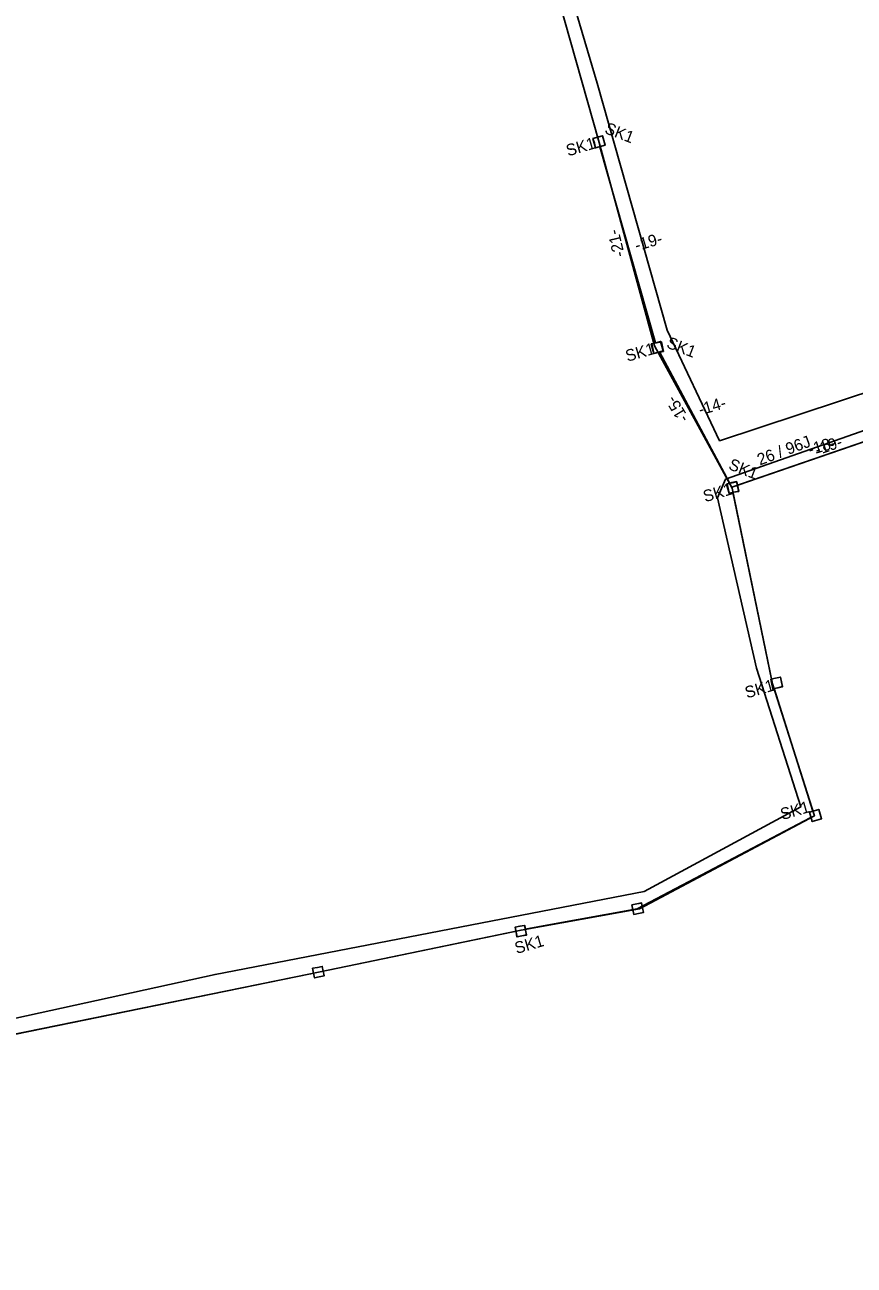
# Model space of a CAD drawing. Extents: x 6494530 to 6506885, y 5884901 to 5892312.
# Drawn here: x 6497551.9 to 6497628.3, y 5889363.3 to 5889477.6 of the extents above; entities that cross this region are included whole.
import ezdxf

# ---------------------------------------------------------------- set-up
doc = ezdxf.new("R2010")
doc.units = 0
for name, color, linetype in [('Gminne - nazwy', 7, 'Continuous'), ('kabel OTK do tablicy VMS', 7, 'Continuous'), ('nr  istniejącego kabla otk', 7, 'Continuous'), ('POWIATOWE', 7, 'Continuous'), ('studnie do wyrysu', 7, 'Continuous'), ('trasa kanalizacji do wyrysu', 7, 'Continuous'), ('W ISTN OTK96J', 7, 'Continuous'), ('Warstwa 59', 7, 'Continuous'), ('WOJEWÓDZKIE', 7, 'Continuous')]:
    doc.layers.add(name, color=color, linetype=linetype)

# ---------------------------------------------------------------- blocks, each defined once
blk = doc.blocks.new('ELARM2_28')
at = {"layer": 'studnie do wyrysu'}
blk.add_lwpolyline([(0, 0.45), (0.45, 0.45), (0.45, 0), (0.45, -0.45), (0, -0.45), (-0.45, -0.45), (-0.45, 0), (-0.45, 0.45)], close=True, dxfattribs=at)
blk = doc.blocks.new('ELARM2_67')
at = {"layer": 'Warstwa 59'}
blk.add_lwpolyline([(0, 0.45), (0.45, 0.45), (0.45, 0), (0.45, -0.45), (0, -0.45), (-0.45, -0.45), (-0.45, 0), (-0.45, 0.45)], close=True, dxfattribs=at)
blk = doc.blocks.new('ELARM2_1')
at = {"layer": 'Warstwa 59'}
blk.add_lwpolyline([(0, 0.45), (0.45, 0.45), (0.45, 0), (0.45, -0.45), (0, -0.45), (-0.45, -0.45), (-0.45, 0), (-0.45, 0.45)], close=True, dxfattribs=at)
blk = doc.blocks.new('ELARM2_66')
at = {"layer": 'Warstwa 59'}
blk.add_lwpolyline([(0, 0.45), (0.45, 0.45), (0.45, 0), (0.45, -0.45), (0, -0.45), (-0.45, -0.45), (-0.45, 0), (-0.45, 0.45)], close=True, dxfattribs=at)

msp = doc.modelspace()

# ---------------------------------------------------------------- linework, layer by layer
at = {"layer": 'kabel OTK do tablicy VMS'}
msp.add_lwpolyline([(6497566.39, 5889591.14), (6497566.7, 5889587.71), (6497574.96, 5889560.77), (6497583.72, 5889538.21), (6497588.6, 5889523.58), (6497595.04, 5889504.58), (6497604.63, 5889472.18), (6497611.08, 5889449.45), (6497615.91, 5889439.25), (6497645.54, 5889449.04), (6497650.66, 5889452.55), (6497656.12, 5889451.35)], dxfattribs=at)
at = {"layer": 'POWIATOWE'}
for points in [[(6497604.87, 5889466.33), (6497610.01, 5889448.28)], [(6497610.36, 5889447.43), (6497616.83, 5889435.38)], [(6497617.59, 5889435.16), (6497633.65, 5889440.68)], [(6497617.14, 5889434.52), (6497620.7, 5889417.31)], [(6497620.92, 5889416.43), (6497624.5, 5889405.15)], [(6497624.31, 5889404.56), (6497608.3, 5889396.16), (6497600, 5889394.64)], [(6497597.16, 5889394.1), (6497578.24, 5889390.15), (6497541.02, 5889382.57)], [(6497600, 5889394.64), (6497598.01, 5889394.27)]]:
    msp.add_lwpolyline(points, dxfattribs=at)
at = {"layer": 'trasa kanalizacji do wyrysu'}
for points in [[(6497608.53, 5889396.14), (6497624.64, 5889404.73), (6497624.64, 5889404.73), (6497620.79, 5889416.88), (6497620.79, 5889416.88), (6497617.06, 5889434.9), (6497617.06, 5889434.9), (6497609.91, 5889448), (6497609.91, 5889448), (6497604.81, 5889466.71), (6497604.81, 5889466.71), (6497593.8, 5889505.66)], [(6497617.05, 5889434.97), (6497634.09, 5889440.83), (6497646.19, 5889445.45), (6497657.16, 5889452.66)], [(6497608.53, 5889396.14), (6497597.63, 5889394.2), (6497578.24, 5889390.15), (6497540.54, 5889382.47), (6497546.64, 5889395.51), (6497506.05, 5889379.42), (6497492.43, 5889369.66), (6497476.31, 5889353.4), (6497455.46, 5889349.47), (6497447.72, 5889347.07), (6497441.59, 5889337.74), (6497453.88, 5889332.27), (6497468.65, 5889330.05)]]:
    msp.add_lwpolyline(points, dxfattribs=at)
at = {"layer": 'W ISTN OTK96J'}
msp.add_lwpolyline([(6497442.42, 5889336.28), (6497442.78, 5889336.03), (6497445.35, 5889340.26), (6497449.03, 5889345.39), (6497455.93, 5889348.23), (6497476.57, 5889351.98), (6497492.83, 5889368.24), (6497505.92, 5889377.92), (6497547.14, 5889394.22), (6497542.37, 5889384.17), (6497569.43, 5889390.11), (6497608.96, 5889397.74), (6497623.38, 5889405.54), (6497619.3, 5889418.32), (6497615.72, 5889433.99), (6497616.46, 5889435.71), (6497645.1, 5889445.78), (6497653.28, 5889451.01), (6497653.33, 5889450.98), (6497654.47, 5889450.18)], dxfattribs=at)
at = {"layer": 'Warstwa 59'}
for points in [[(6497605.23, 5889466.9), (6497605.36, 5889466.47), (6497604.92, 5889466.35), (6497604.49, 5889466.22), (6497604.37, 5889466.66), (6497604.24, 5889467.09), (6497604.68, 5889467.21), (6497605.11, 5889467.34)], [(6497610.28, 5889447.42), (6497609.84, 5889447.3), (6497609.73, 5889447.73), (6497609.61, 5889448.17), (6497610.04, 5889448.28), (6497610.48, 5889448.4), (6497610.59, 5889447.97), (6497610.71, 5889447.53)], [(6497617.57, 5889435.06), (6497617.67, 5889434.62), (6497617.23, 5889434.52), (6497616.79, 5889434.42), (6497616.69, 5889434.86), (6497616.59, 5889435.3), (6497617.03, 5889435.4), (6497617.47, 5889435.5)], [(6497617.57, 5889435.06), (6497617.67, 5889434.62), (6497617.23, 5889434.52), (6497616.79, 5889434.42), (6497616.69, 5889434.86), (6497616.59, 5889435.3), (6497617.03, 5889435.4), (6497617.47, 5889435.5)], [(6497621.61, 5889417.05), (6497621.71, 5889416.61), (6497621.27, 5889416.51), (6497620.83, 5889416.41), (6497620.73, 5889416.85), (6497620.63, 5889417.29), (6497621.07, 5889417.39), (6497621.51, 5889417.49)], [(6497625.17, 5889404.88), (6497625.3, 5889404.45), (6497624.87, 5889404.32), (6497624.44, 5889404.19), (6497624.31, 5889404.62), (6497624.18, 5889405.05), (6497624.61, 5889405.18), (6497625.04, 5889405.31)], [(6497598.04, 5889394.19), (6497598.13, 5889393.74), (6497597.69, 5889393.66), (6497597.24, 5889393.57), (6497597.16, 5889394.01), (6497597.07, 5889394.46), (6497597.52, 5889394.54), (6497597.96, 5889394.63)]]:
    msp.add_lwpolyline(points, close=True, dxfattribs=at)

# ---------------------------------------------------------------- block references
at = {"layer": 'studnie do wyrysu'}
for p, xscale, yscale, rotation in [((6497604.8, 5889466.78), 0.9999978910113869, 0.999997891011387, -74.07570327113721), ((6497610.2, 5889447.83), 0.9999978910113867, 0.9999978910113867, -78.60251249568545), ((6497617.14, 5889434.95), 0.9999978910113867, 0.9999978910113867, -78.60251249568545), ((6497621.16, 5889416.94), 0.9999978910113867, 0.9999978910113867, -78.60251249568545), ((6497624.74, 5889404.75), 0.999997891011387, 0.9999978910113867, -73.22777200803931), ((6497608.36, 5889396.16), 0.9999978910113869, 0.9999978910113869, -78.61769077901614), ((6497597.6, 5889394.1), 0.9999978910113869, 0.9999978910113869, -78.61769077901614), ((6497578.95, 5889390.32), 0.9999978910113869, 0.9999978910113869, -78.61769077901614)]:
    msp.add_blockref('ELARM2_28', p, dxfattribs=dict(at, xscale=xscale, yscale=yscale, rotation=rotation))
at = {"layer": 'Warstwa 59'}
for name, p, xscale, yscale, rotation in [('ELARM2_67', (6497604.8, 5889466.78), 1.0000006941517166, 1.000000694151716, -74.03180878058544), ('ELARM2_67', (6497610.16, 5889447.85), 0.9999979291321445, 0.9999979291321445, -164.81533982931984), ('ELARM2_1', (6497617.13, 5889434.96), 1.000001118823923, 1.0000011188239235, -77.35676739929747), ('ELARM2_1', (6497621.17, 5889416.95), 1.000001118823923, 1.0000011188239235, -77.35676739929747), ('ELARM2_66', (6497624.74, 5889404.75), 1.0000006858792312, 1.0000006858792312, -73.26326622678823), ('ELARM2_66', (6497608.36, 5889396.16), 0.9999990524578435, 0.9999990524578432, -79.16868766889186), ('ELARM2_66', (6497597.6, 5889394.1), 0.9999990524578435, 0.9999990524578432, -79.16868766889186), ('ELARM2_67', (6497578.95, 5889390.32), 1.0000018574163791, 1.000001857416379, 11.269223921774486)]:
    msp.add_blockref(name, p, dxfattribs=dict(at, xscale=xscale, yscale=yscale, rotation=rotation))

# ---------------------------------------------------------------- texts
at = {"layer": 'Gminne - nazwy'}
for p in [(6497601.95, 5889465.44), (6497607.42, 5889446.52), (6497614.57, 5889433.59), (6497618.42, 5889415.52), (6497621.69, 5889404.32), (6497597.21, 5889391.99)]:
    msp.add_text('SK1', height=1.075, rotation=16.2521, dxfattribs=at).set_placement(p)
at = {"layer": 'nr  istniejącego kabla otk'}
msp.add_text('26 / 96J', height=1.075, rotation=20.5146, dxfattribs=at).set_placement((6497619.61, 5889436.97))
at = {"layer": 'studnie do wyrysu'}
for p in [(6497605.24, 5889467.61), (6497610.94, 5889447.86), (6497616.65, 5889436.66)]:
    msp.add_text('SK1', height=1.075, rotation=338.8705, dxfattribs=at).set_placement(p)
at = {"layer": 'trasa kanalizacji do wyrysu'}
for s, rotation, p in [('-21-', 103.4964, (6497607.19, 5889456.31)), ('-15-', 121.1979, (6497613.12, 5889441.33)), ('-19-', 19.2708, (6497624.9, 5889437.89))]:
    msp.add_text(s, height=1.075, rotation=rotation, dxfattribs=at).set_placement(p)
at = {"layer": 'WOJEWÓDZKIE'}
for s, p in [('-19-', (6497608.27, 5889456.71)), ('-14-', (6497614.14, 5889441.59)), ('-18-', (6497624.25, 5889437.91))]:
    msp.add_text(s, height=1.075, rotation=16.2624, dxfattribs=at).set_placement(p)

doc.saveas('drawing.dxf')
